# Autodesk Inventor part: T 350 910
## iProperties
Company: Mayer & Müller AG Schaltgeräte
Created: 2006-01
Part Number: T 350 910
Material: 2.0060.30
Document SubType Name: Sheet Metal
Designer: I.Baliuc
Manufacturer: Standard
Standards Organization: Custom
Description: Spulensockel
Density: 8.94 g/cm^3
Sheet Metal Rule: Standard
HalbzeugNorm: DIN 1759
Zweck: zum Lichtbogenabreißer
Abmessung: 30x4-119,6
Author: T.Messerschmitt
Revision Number: 350910
Keywords: 382210
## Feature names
1. Bohrung_Ø3 [Hole]
2. Bohrung_Ø6.2 [Hole]
3. Extrusion_R1.5-38
4. Grobblech1
5. Biegung1
6. ExtrusionAbwicklung2
